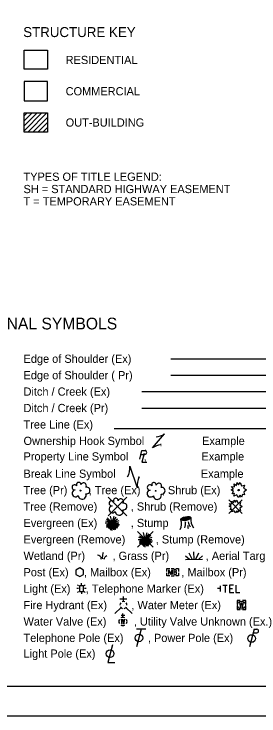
# Model space of a CAD drawing. Extents: x 0 to 70.6, y 0 to 31.9.
# Drawn here: x 8.1 to 12.28, y 0 to 11.97 of the extents above; entities that cross this region are included whole.
import ezdxf

# ---------------------------------------------------------------- set-up
doc = ezdxf.new("R2010")
doc.units = 0
for name, color, linetype in [('GM_X_Adjacent_County', 7, 'Continuous'), ('GM_X_County', 7, 'Continuous'), ('GM_X_Section', 7, 'Continuous'), ('GM_X_US_Shield', 7, 'Continuous')]:
    doc.layers.add(name, color=color, linetype=linetype)

msp = doc.modelspace()

# ---------------------------------------------------------------- linework, layer by layer
at = {"layer": 'GM_X_Adjacent_County'}
for p, q in [((8.275, 10.281), (8.276, 10.282)), ((8.275, 10.231), (8.326, 10.282)), ((8.275, 10.146), (8.411, 10.282)), ((8.275, 10.061), (8.495, 10.282)), ((8.275, 9.976), (8.58, 10.282)), ((8.339, 9.956), (8.665, 10.282)), ((8.424, 9.956), (8.672, 10.204)), ((8.508, 9.956), (8.672, 10.119)), ((8.275, 9.961), (8.279, 9.956)), ((8.593, 9.956), (8.672, 10.035)), ((10.782, 6.091), (14.265, 6.091)), ((10.782, 5.811), (14.265, 5.811)), ((10.282, 5.531), (14.182, 5.531)), ((10.282, 5.251), (14.182, 5.251)), ((9.814, 4.901), (14.164, 4.901)), ((10.469, 4.571), (10.669, 4.811)), ((10.569, 4.691), (10.569, 4.691)), ((10.269, 4.46), (10.334, 4.46)), ((10.309, 4.429), (10.309, 4.429)), ((10.077, 4.259), (10.207, 3.891)), ((10.142, 4.075), (10.142, 4.075)), ((9.709, 3.731), (10.03, 3.411)), ((10.03, 3.731), (9.709, 3.411)), ((11.768, 3.687), (12, 3.455)), ((12, 3.687), (11.768, 3.455)), ((9.87, 3.571), (9.87, 3.571)), ((11.884, 3.571), (11.884, 3.571)), ((9.78, 3.291), (9.693, 3.378)), ((9.78, 3.291), (9.749, 3.406)), ((9.78, 3.291), (9.812, 3.408)), ((9.78, 3.291), (9.847, 3.388)), ((9.78, 3.291), (9.872, 3.361)), ((9.657, 3.291), (9.78, 3.291)), ((9.78, 3.291), (9.67, 3.32)), ((9.78, 3.291), (9.673, 3.252)), ((9.78, 3.291), (9.681, 3.234)), ((9.78, 3.291), (9.683, 3.348)), ((9.78, 3.291), (9.683, 3.216)), ((9.78, 3.291), (9.707, 3.204)), ((9.78, 3.291), (9.722, 3.19)), ((9.78, 3.291), (9.739, 3.182)), ((9.78, 3.291), (9.749, 3.169)), ((9.78, 3.291), (9.767, 3.176)), ((9.78, 3.291), (9.899, 3.331)), ((9.78, 3.291), (9.893, 3.293)), ((9.78, 3.16), (9.78, 3.291)), ((9.78, 3.291), (9.803, 3.175)), ((9.78, 3.291), (9.829, 3.174)), ((9.78, 3.291), (9.844, 3.196)), ((9.78, 3.291), (9.87, 3.203)), ((9.78, 3.291), (9.876, 3.227)), ((9.78, 3.291), (9.892, 3.242)), ((9.78, 3.291), (9.901, 3.267)), ((11.054, 3.291), (11.054, 3.291)), ((10.211, 3.145), (10.478, 2.877)), ((10.478, 3.145), (10.211, 2.877)), ((10.344, 3.011), (10.313, 3.126)), ((10.344, 3.011), (10.376, 3.128)), ((10.221, 3.011), (10.344, 3.011)), ((10.344, 3.011), (10.234, 3.041)), ((10.344, 3.011), (10.237, 2.972)), ((10.344, 3.011), (10.245, 2.954)), ((10.344, 3.011), (10.247, 3.068)), ((10.344, 3.011), (10.247, 2.936)), ((10.344, 3.011), (10.257, 3.098)), ((10.344, 3.011), (10.271, 2.924)), ((10.344, 3.011), (10.286, 2.911)), ((10.344, 3.011), (10.303, 2.902)), ((10.344, 3.011), (10.313, 2.89)), ((10.344, 3.011), (10.331, 2.896)), ((10.344, 3.011), (10.411, 3.108)), ((10.344, 3.011), (10.436, 3.081)), ((10.344, 3.011), (10.463, 3.051)), ((10.344, 3.011), (10.457, 3.013)), ((10.344, 2.88), (10.344, 3.011)), ((10.344, 3.011), (10.367, 2.895)), ((10.344, 3.011), (10.393, 2.894)), ((10.344, 3.011), (10.408, 2.916)), ((10.344, 3.011), (10.434, 2.923)), ((10.344, 3.011), (10.44, 2.947)), ((10.344, 3.011), (10.456, 2.962)), ((10.344, 3.011), (10.465, 2.987)), ((10.344, 3.011), (10.344, 3.011)), ((11.146, 2.671), (11.094, 2.777)), ((11.176, 2.671), (11.174, 2.796)), ((11.206, 2.671), (11.255, 2.779)), ((11.097, 2.67), (11.029, 2.727)), ((11.03, 2.669), (11.322, 2.673)), ((11.255, 2.672), (11.321, 2.731)), ((10.787, 2.512), (10.837, 2.512)), ((10.813, 2.451), (10.813, 2.451)), ((10.787, 2.39), (10.837, 2.39)), ((9.201, 2.171), (9.174, 2.171)), ((9.205, 2.219), (9.186, 2.238)), ((9.253, 2.235), (9.253, 2.262)), ((9.253, 2.171), (9.253, 2.171)), ((9.32, 2.238), (9.301, 2.219)), ((9.332, 2.171), (9.305, 2.171)), ((11.626, 2.171), (11.576, 2.171)), ((11.626, 2.121), (11.626, 2.221)), ((9.205, 2.123), (9.186, 2.104)), ((9.253, 2.107), (9.253, 2.08)), ((9.32, 2.104), (9.301, 2.123)), ((9.971, 1.951), (9.971, 2.037)), ((10.031, 1.994), (9.911, 1.994)), ((9.929, 1.849), (9.825, 1.745)), ((9.971, 1.891), (9.971, 1.891)), ((9.971, 1.891), (9.971, 1.891)), ((10.013, 1.849), (10.117, 1.745)), ((11.985, 1.891), (11.985, 1.891)), ((9.994, 1.713), (9.93, 1.713)), ((9.962, 1.681), (9.962, 1.745)), ((9.962, 1.611), (9.962, 1.611)), ((10.355, 1.481), (10.195, 1.481)), ((10.275, 1.481), (10.195, 1.181)), ((12.204, 1.481), (12.124, 1.181)), ((12.204, 1.481), (12.246, 1.481)), ((12.187, 1.417), (12.246, 1.417))]:
    msp.add_line(p, q, dxfattribs=at)
for points in [[(8.275, 11.353), (8.672, 11.353), (8.672, 11.027), (8.275, 11.027)], [(8.275, 10.282), (8.672, 10.282), (8.672, 9.956), (8.275, 9.956)], [(9.22, 2.121), (9.286, 2.121), (9.286, 2.221), (9.22, 2.221)]]:
    msp.add_lwpolyline(points, close=True, dxfattribs=at)
for points in [[(10.248, 4.38), (10.287, 4.529), (10.339, 4.529)], [(10.323, 4.477), (10.283, 4.329), (10.37, 4.329)], [(11.933, 3.941), (11.963, 3.978), (11.984, 3.926), (12.039, 3.935), (12.022, 3.884), (12.069, 3.854), (12.026, 3.817), (12.039, 3.772), (12.001, 3.775), (11.985, 3.73), (11.963, 3.764), (11.929, 3.723), (11.908, 3.768), (11.857, 3.746), (11.867, 3.793), (11.826, 3.789), (11.85, 3.829), (11.811, 3.857), (11.848, 3.87), (11.818, 3.91), (11.864, 3.905), (11.863, 3.957), (11.901, 3.928), (11.911, 3.978), (11.933, 3.941)], [(11.881, 3.648), (11.906, 3.679), (11.924, 3.634), (11.97, 3.642), (11.956, 3.599), (11.996, 3.574), (11.96, 3.542), (11.97, 3.504), (11.938, 3.507), (11.925, 3.468), (11.906, 3.497), (11.878, 3.462), (11.859, 3.5), (11.816, 3.482), (11.824, 3.522), (11.79, 3.518), (11.81, 3.552), (11.777, 3.576), (11.809, 3.587), (11.783, 3.621), (11.822, 3.617), (11.821, 3.661), (11.853, 3.637), (11.862, 3.679), (11.881, 3.648)], [(9.16, 2.413), (9.225, 2.376), (9.29, 2.413), (9.29, 2.488), (9.225, 2.526), (9.16, 2.488), (9.16, 2.413)], [(10.713, 2.464), (10.713, 2.512), (10.761, 2.512)], [(10.761, 2.39), (10.713, 2.39), (10.713, 2.438)], [(10.748, 2.411), (10.748, 2.491), (10.777, 2.411), (10.804, 2.491), (10.804, 2.411)], [(10.864, 2.454), (10.867, 2.458), (10.869, 2.459), (10.87, 2.461), (10.871, 2.463), (10.872, 2.465), (10.872, 2.467), (10.874, 2.471), (10.874, 2.473), (10.874, 2.476), (10.873, 2.48), (10.872, 2.483), (10.87, 2.485), (10.867, 2.488), (10.864, 2.489), (10.863, 2.49), (10.86, 2.491), (10.829, 2.491), (10.829, 2.411), (10.864, 2.411), (10.868, 2.413), (10.872, 2.417), (10.875, 2.422), (10.877, 2.427), (10.878, 2.433), (10.878, 2.437), (10.876, 2.441), (10.874, 2.446), (10.871, 2.45), (10.864, 2.454), (10.829, 2.454)], [(10.863, 2.512), (10.913, 2.512), (10.913, 2.464)], [(10.913, 2.438), (10.913, 2.39), (10.863, 2.39)], [(11.666, 2.233), (11.744, 2.233)], [(11.706, 2.233), (11.706, 2.108)], [(11.851, 2.233), (11.783, 2.233), (11.783, 2.108), (11.856, 2.108)], [(11.783, 2.171), (11.832, 2.171)], [(11.891, 2.233), (11.891, 2.108), (11.959, 2.108)], [(11.965, 1.966), (11.91, 1.966), (11.91, 1.911)], [(11.951, 1.936), (11.968, 1.846), (11.985, 1.936), (12.001, 1.846), (12.018, 1.936)], [(12.06, 1.911), (12.06, 1.966), (12.005, 1.966)], [(11.91, 1.871), (11.91, 1.816), (11.965, 1.816)], [(12.005, 1.816), (12.06, 1.816), (12.06, 1.871)], [(9.93, 1.652), (9.946, 1.566), (9.962, 1.652), (9.978, 1.566), (9.994, 1.652)], [(9.782, 1.21), (9.703, 0.91), (9.822, 0.91)]]:
    msp.add_lwpolyline(points, dxfattribs=at)
for centre, radius in [((9.237, 3.843), 0.0084), ((10.521, 3.839), 0.0072), ((11.937, 3.851), 0.0115), ((9.87, 3.571), 0.0072), ((11.884, 3.571), 0.00979), ((11.985, 1.891), 0.0675), ((10.235, 1.331), 0.065), ((12.161, 1.321), 0.065), ((9.743, 1.062), 0.065)]:
    msp.add_circle(centre, radius, dxfattribs=at)
for centre, radius, start, end in [((10.511, 5.026), 0.267, 273.6945, 306.337), ((10.627, 4.356), 0.267, 93.6945, 126.337), ((10.334, 4.494), 0.0345, 270.471, 81.3281), ((9.745, 4.227), 0.334, 332.9422, 5.5848), ((10.538, 3.924), 0.334, 152.9422, 185.5848), ((9.207, 3.944), 0.0395, 354.0047, 205.9741), ((9.291, 3.928), 0.0466, 323.83, 165.0376), ((10.492, 3.94), 0.0395, 354.0047, 205.9741), ((10.576, 3.924), 0.0466, 323.83, 165.0376), ((9.151, 3.796), 0.0592, 96.1722, 320.5737), ((9.137, 3.899), 0.0441, 39.0625, 279.5412), ((9.341, 3.844), 0.0574, 259.1453, 101.4596), ((10.436, 3.793), 0.0592, 96.1722, 320.5737), ((10.422, 3.895), 0.0441, 39.0625, 279.5412), ((10.625, 3.84), 0.0574, 259.1453, 101.4596), ((9.265, 3.765), 0.0685, 184.9476, 19.4572), ((9.84, 3.672), 0.0395, 354.0047, 205.9741), ((10.55, 3.761), 0.0685, 184.9476, 19.4572), ((9.77, 3.627), 0.0441, 39.0625, 279.5412), ((9.924, 3.656), 0.0466, 323.83, 165.0376), ((9.974, 3.572), 0.0574, 259.1453, 101.4596), ((9.784, 3.524), 0.0592, 96.1722, 320.5737), ((9.898, 3.493), 0.0685, 184.9476, 19.4572), ((11.334, 3.348), 0.215, 171.4106, 219.9194), ((10.762, 3.274), 0.2, 331.5338, 20.9269), ((10.778, 3.292), 0.253, 340.7938, 3.5481), ((11.249, 3.251), 0.182, 178.7926, 197.1224), ((11.379, 3.394), 0.316, 194.9653, 212.1216), ((9.971, 1.891), 0.06, 140.021, 184.0629), ((9.971, 1.891), 0.06, 68.1395, 112.038), ((9.971, 1.891), 0.06, 356.0165, 39.9889), ((9.971, 1.891), 0.06, 211.8788, 255.8479), ((9.971, 1.891), 0.06, 283.8239, 329.9097), ((9.962, 1.611), 0.07, 60.0184, 120.0157), ((9.962, 1.611), 0.07, 150.0184, 209.9816), ((9.962, 1.611), 0.07, 330.0184, 29.9816), ((9.962, 1.611), 0.07, 239.9843, 299.9816), ((12.247, 1.449), 0.0319, 268.8767, 91.1233)]:
    msp.add_arc(centre, radius, start, end, dxfattribs=at)
for major_axis in [(0.0868, 0.0187), (0.0651, 0.0141), (0.0488, 0.0105), (0.0275, 0.0059), (0.0154, 0.0033)]:
    msp.add_ellipse((11.035, 3.366), major_axis=major_axis, ratio=0.36865, dxfattribs=at)
for points in [[(9.616, 2.68), (9.616, 2.727), (9.622, 2.771), (9.631, 2.792)], [(9.529, 2.747), (9.57, 2.729), (9.588, 2.676)], [(9.644, 2.672), (9.656, 2.711), (9.685, 2.735)]]:
    msp.add_spline(points, degree=3, dxfattribs=at)
at = {"layer": 'GM_X_County'}
msp.add_lwpolyline([(1.5, 21.5), (33.5, 21.5), (33.5, 0.5), (1.5, 0.5)], close=True, dxfattribs=at)
at = {"layer": 'GM_X_Section'}
msp.add_lwpolyline([(0, 0), (34, 0), (34, 22), (0, 22)], close=True, dxfattribs=at)
at = {"layer": 'GM_X_US_Shield'}
msp.add_lwpolyline([(8.275, 10.491), (8.672, 10.491), (8.672, 10.817), (8.275, 10.817)], close=True, dxfattribs=at)

# ---------------------------------------------------------------- texts
at = {"layer": 'GM_X_Adjacent_County'}
for s, height, p in [('STRUCTURE KEY', 0.17, (8.259, 11.576)), ('RESIDENTIAL', 0.14, (8.984, 11.116)), ('COMMERCIAL', 0.14, (8.984, 10.582)), ('OUT-BUILDING', 0.14, (8.984, 10.049)), ('TYPES OF TITLE LEGEND:', 0.14, (8.265, 9.125)), ('SH = STANDARD HIGHWAY EASEMENT', 0.14, (8.265, 8.915)), ('T = TEMPORARY EASEMENT', 0.14, (8.265, 8.705)), ('CONVENTIONAL SYMBOLS', 0.2, (6.386, 6.591)), ('Edge of Shoulder (Ex)', 0.14, (8.265, 6.021)), ('Edge of Shoulder ( Pr)', 0.14, (8.265, 5.741)), ('Ditch / Creek (Ex)', 0.14, (8.265, 5.461)), ('Ditch / Creek (Pr)', 0.14, (8.265, 5.181)), ('Tree Line (Ex)', 0.14, (8.265, 4.901)), ('Ownership Hook Symbol     ,             Example', 0.14, (8.265, 4.621)), ('Property Line Symbol     ,                  Example', 0.14, (8.265, 4.356)), ('Break Line Symbol       ,                    Example', 0.14, (8.265, 4.061)), ('Tree (Pr)       , Tree (Ex)       , Shrub (Ex)', 0.14, (8.265, 3.781)), ('Tree (Remove)           , Shrub (Remove)', 0.14, (8.265, 3.501)), ('Evergreen (Ex)           , Stump ', 0.14, (8.265, 3.221)), ('Evergreen (Remove)          , Stump (Remove)', 0.14, (8.265, 2.941)), ('Wetland (Pr)         , Grass (Pr)            , Aerial Target    ', 0.14, (8.265, 2.661)), ('Post (Ex)     , Mailbox (Ex)          , Mailbox (Pr)', 0.14, (8.265, 2.381)), ('Light (Ex)     , Telephone Marker (Ex)     ', 0.14, (8.265, 2.101)), ('Fire Hydrant (Ex)        , Water Meter (Ex)', 0.14, (8.265, 1.821)), ('Water Valve (Ex)         , Utility Valve Unknown (Ex.)', 0.14, (8.265, 1.541)), ('Telephone Pole (Ex)        , Power Pole (Ex)', 0.14, (8.265, 1.261)), ('Light Pole (Ex)     ', 0.14, (8.265, 0.994))]:
    msp.add_text(s, height=height, dxfattribs=at).set_placement(p)

doc.saveas('drawing.dxf')
